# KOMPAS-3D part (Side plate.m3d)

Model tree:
1. X Axis
2. Y Axis
3. Z Axis
4. Origin
     Wall Thickness 1 = 1; Wall Thickness 2 = 1; Distance 1 = 10; Distance 2 = 10

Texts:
  Steel DIN 17102
  Three Point Plane
  Plane at Angle
  Line and Point Plane
  Axis through Two Vertices
  Axis of Feature
  Axis of Conical Surface
  Axis through Edge
  Trim by Surface
  Trim by Sketch
  Feature with No History
  Intersection Axis of Two Planes
  Two Line Plane
  Line and Face Plane
  Bend by line
  Hole in sheet body
  Cut in sheet body
  Point in CM
  Linear Dimension from Line to Point
  Surface Finish Symbol
  Geometric Tolerance Symbol
  Leader #1
  Leader #2
  Leader #3
  Shape Deviations and Datum
  Node point number
  Mark of coordination axis
  Node point designation
  Mark/Reference designation with leader
  Mark/reference designation on line
  Mark/Reference designation without leader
